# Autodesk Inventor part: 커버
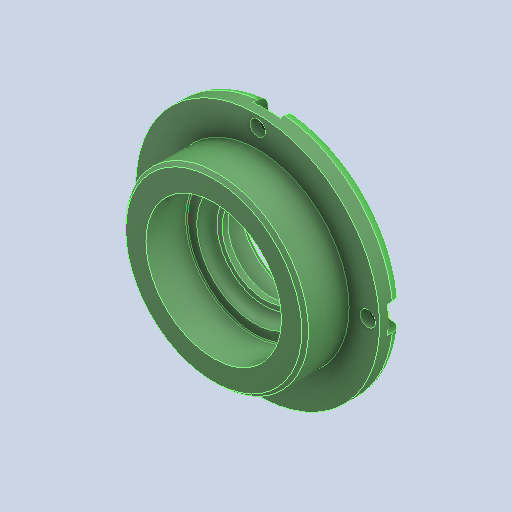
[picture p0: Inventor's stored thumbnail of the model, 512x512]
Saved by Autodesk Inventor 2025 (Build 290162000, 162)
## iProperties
Created: 2024-07
Part Number: 커버
Material: 강철, 연강
Document SubType Name: Modeling
Designer: 학생
Density: 7.86 g/cm^3
Appearance: 기본값
Company: 한국ATC센터
Author: jhkim
Revision Number: 1
Sending System: Autodesk Inventor 2025
Preprocessor: ST-DEVELOPER v20
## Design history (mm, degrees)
feature "솔리드1"
node "솔리드2"
